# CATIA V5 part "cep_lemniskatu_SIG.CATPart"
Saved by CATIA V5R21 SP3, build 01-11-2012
Part number: cep_lemniskatu_SIG
Material "Steel": density 7860 kg/m3, Young's modulus 2e+11 Pa, Poisson ratio 0.266, thermal expansion 1.17e-05 1/K
Bounding box of the stored display mesh (mm): x -260 to 260, y -453.616 to 530, z 0 to 244
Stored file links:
  C:\Users\Martin\Desktop\vzduchove naklapeni\12\cep_lemniskatu_SIG.CATPart
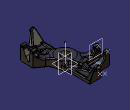
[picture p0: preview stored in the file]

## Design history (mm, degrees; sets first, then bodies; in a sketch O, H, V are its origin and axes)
Set1
  Plane1: type Offset, RefPlane zx-plane, Offset 400
  Plane2: type Offset, RefPlane face of Pad3, Offset 50
  Point1: (0, 0, 0)
  Line1: type PtDir, RefPoint Point1, Direction edge [face of Pad2 from Sketch2.L4 | start face of Pad2], Start 0, End 244
  Plane3: type Angle, RefPlane yz-plane, Direction Line1, Angle 45
  Line2: stored without definition
  Point2: stored without definition
  Plane4: type Offset, RefPlane face of Pad4, Offset 15
  Point3: (0, 470, 150)
  Point4: (0, 460, 110)
  Point5: type Center, Curve edge [face of Pad4 | face of Hole2]
  Point6: type Center, Curve edge [face of Pad4 | face of Hole1]
  Point7: type Between, FirstPoint Point6, SecondPoint Point5, Ratio 0.5
  Line3: type PtDir, RefPoint Point7, Direction edge [face of Pad5 from Sketch6.L1 | face of Pad4], Start -149, End 244
  Plane5: type 2Lines, Element1 Line3, Element2 Line1
  Plane6: type Offset, RefPlane face of Pad6, Offset 30
Body1 (main body)
  Sketch1 on xy-plane, origin (0, 0, 0), H (1, 0, 0), V (0, 1, 0)
    circle A1 centre (0, 0) radius 55
    circle A2 centre (0, 0) radius 115
    radius A1 = 55
    radius A2 = 115
  Pad1: profile Sketch1, direction (0, 0, 1), length 110
  Sketch2 on Plane1, origin (0, 400, 0), H (-1, 0, 0), V (0, 0, 1)
    line L1 (-45, 30) -> (45, 30)
    line L2 (75, 45) -> (75, 0)
    line L3 (75, 0) -> (-75, 0)
    line L4 (-75, 0) -> (-75, 45)
    reference projected line E1 (-115, 0) -> (115, 0) from edge [start face of Pad1 | face of Pad1 from Sketch1.A2]
    reference projected line E2 through (0, 0) direction (0, 1) from axis of face of Pad1 from Sketch1.A2
    reference projected line E3 (-115, 0) -> (115, 0) from edge [start face of Pad1 | face of Pad1 from Sketch1.A2]
    line L5 (-45, 45) -> (-45, 30)
    line L6 (45, 45) -> (75, 45)
    line L7 (45, 30) -> (45, 45)
    point P7 (75, 45)
    line L8 (-75, 45) -> (-45, 45)
    distance L4 L2 = 150
    distance E2 L4 = 75
    distance L1 E3 = 30
    distance L1 L6 = 15
    distance L5 L4 = 30
    distance L7 L2 = 30
    distance L8 L1 = 15
    horizontal: L1 H, L3 H, L6 H, L8 H
    vertical: L2 V, L4 V, L5 V, L7 V
    coincidence: E1 L3, P7 L6
  Pad2: profile Sketch2, direction (0, 1, 0), up to the existing solid (limit type 2)
  Sketch3 on face of Pad2, origin (-75, 0, 0), H (0, -1, 0), V (0, 0, 1)
    line L1 (-325, 45) -> (-280, 45)
    line L2 (-280, 45) -> (-280, 40)
    line L3 (-160, 0) -> (-325, 0)
    line L4 (-325, 0) -> (-325, 45)
    line L5 (-205, 45) -> (-160, 45)
    line L6 (-160, 45) -> (-160, 0)
    line L7 (-205, 40) -> (-205, 45)
    line L8 (-280, 40) -> (-205, 40)
    reference projected line E1 (-400, 0) -> (-87.178, 0) from edge [face of Pad2 | face of Pad2]
    reference projected line E2 through (0, 0) direction (0, 1) from axis of face of Pad1 from Sketch1.A1
    reference projected line E3 (-400, 45) -> (-87.178, 45) from edge [face of Pad2 from Sketch2.L2 | face of Pad2 from Sketch2.L6]
    reference projected line E4 (-400, 45) -> (-87.178, 45) from edge [face of Pad2 from Sketch2.L2 | face of Pad2 from Sketch2.L6]
    distance L8 L3 = 40
    distance L7 L6 = 45
    distance L4 L2 = 45
    distance E2 L6 = 160
    distance L2 L7 = 75
    horizontal: L1 H, L3 H, L5 H, L8 H
    vertical: L2 V, L4 V, L6 V, L7 V
    coincidence: L3 E1, L1 E3, L5 E4
  Pad3: profile Sketch3, direction (-1, 0, 0), length 185
  Sketch4 on face of Pad3 from Sketch3.L1, origin (0, 0, 45), H (1, 0, 0), V (0, 1, 0)
    line L1 (-260, 325) -> (-200, 325)
    line L2 (-200, 280) -> (-260, 280)
    line L3 (-260, 280) -> (-260, 325)
    reference projected line E1 (-75, 325) -> (-260, 325) from edge [face of Pad3 from Sketch3.L4 | face of Pad3 from Sketch3.L1]
    reference projected line E2 (-75, 280) -> (-260, 280) from edge [face of Pad3 from Sketch3.L1 | face of Pad3 from Sketch3.L2]
    reference projected line E3 (-260, 280) -> (-260, 325) from edge [face of Pad3 from Sketch3.L1 | end face of Pad3]
    point P3 (-260, 205)
    line L4 (-260, 205) -> (-200, 205)
    line L5 (-200, 160) -> (-260, 160)
    line L6 (-260, 160) -> (-260, 205)
    reference projected line E4 (-75, 160) -> (-260, 160) from edge [face of Pad3 | face of Pad3 from Sketch3.L6]
    reference projected line E5 (-75, 205) -> (-260, 205) from edge [face of Pad3 from Sketch3.L7 | face of Pad3]
    reference projected line E6 (-260, 160) -> (-260, 205) from edge [face of Pad3 | face of Pad3]
    point P5 (-208, 205)
    point P6 (-200, 280)
    line L7 (-200, 325) -> (-200, 280)
    line L8 (-200, 160) -> (-200, 205)
    distance P5 P3 = 52
    distance P6 L3 = 60
    horizontal: L1 H, L2 H, L4 H, L5 H
    vertical: L3 V, L6 V, L7 V, L8 V
    coincidence: L1 E1, L2 E2, E3 L3, L5 E4, L4 E5, E6 L6, P5 L4, L8 L7
  Pad4: profile Sketch4, direction (0, 0, 1), length 140
  Sketch5 on face of Pad4, origin (-260, 321.6842, 147.6114), H (0, 1, 0), V (0, 0, -1)
    point P1 (-11.6842, -17.3886)
    reference projected line E1 (3.3158, 102.6114) -> (3.3158, 147.6114) from edge [face of Pad4 | face of Pad4]
    reference projected line E2 (-116.6842, -37.3886) -> (-161.6842, -37.3886) from edge [face of Pad4 | end face of Pad4]
    distance P1 E1 = 15
    distance P1 E2 = 20
  Hole1: placed by Sketch5, at (-260, 310, 165) direction (1, 0, 0), diameter 20, depth 44
  Sketch6 on Plane2, origin (0, 0, 50), H (1, 0, 0), V (0, 1, 0)
    line L1 (-260, 160) -> (-104.837, 47.2675)
    line L2 (-75, 160) -> (-75, 87.178)
    projected circle E1 centre (0, 0) radius 115 from edge [face of Pad1 from Sketch1.A2 | end face of Pad1]
    projected arc E2 centre (0, 0) radius 115 from (-75, 87.178) to (-104.837, 47.2675) ccw from edge [face of Pad1 from Sketch1.A2 | end face of Pad1]
    point P1 (-260, 160)
    point P3 (-75, 87.178)
    point P4 (-75, 160)
    construction line L3 (-251.8954, 176.379) -> (48.2139, -33.7597)
    reference projected point E3 (-260, 160) from vertex [face of Pad4 | end face of Pad4 | face of Pad4]
    reference projected point E4 (-75, 87.178) from vertex [face of Pad2 from Sketch2.L2 | face of Pad3 | face of Pad1 from Sketch1.A2]
    reference projected point E5 (-75, 160) from vertex [face of Pad3 from Sketch3.L6 | face of Pad2 from Sketch2.L2 | face of Pad3]
    projected line E6 (-260, 160) -> (-200, 160) from edge [face of Pad4 | end face of Pad4]
    projected line E7 (-75, 160) -> (-200, 160) from edge [face of Pad3 | face of Pad4]
    angle L1 L3 = 1
    angle L3 H = 35
    coincidence: P1 E3, L3 O, P3 E4, P4 E5
  Pad5: profile Sketch6, direction (0, 0, 1), length 40, opposite side length 50
  Sketch7 on face of Pad4, origin (-260, 177.7691, 148.1263), H (0, 1, 0), V (0, 0, -1)
    point P1 (2.2309, -16.8737)
    reference projected line E1 (27.2309, -36.8737) -> (-17.7691, -36.8737) from edge [face of Pad4 | end face of Pad4]
    reference projected line E3 (27.2309, 103.1263) -> (27.2309, 108.1263) from edge [face of Pad4 | face of Pad4]
    distance P1 E1 = 20
    distance P1 E3 = 25
  Hole2: placed by Sketch7, at (-260, 180, 165) direction (1, 0, 0), diameter 20, depth 44
  Sketch8 on face of Pad4 from Sketch4.L8, origin (-200, 0, 0), H (0, 1, 0), V (0, 0, 1)
    line L1 (160, 90) -> (205, 90)
    line L2 (205, 90) -> (205, 45)
    reference projected line E1 (160, 90) -> (47.2675, 90) from edge [face of Pad5 from Sketch6.L1 | end face of Pad5]
    reference projected line E2 (205, 45) -> (205, 185) from edge [face of Pad4 | face of Pad4 from Sketch4.L8]
    projected line E3 (160, 45) -> (205, 45) from edge [face of Pad3 | face of Pad4 from Sketch4.L8]
    projected line E4 (160, 45) -> (160, 90) from edge [face of Pad4 from Sketch4.L8 | face of Pad5 from Sketch6.E7]
    horizontal: L1 H
    vertical: L2 V
    coincidence: E1 L1, L2 E2
  Pad6: profile Sketch8, direction (1, 0, 0), up to face of Pad2 from Sketch2.L2
  Sketch9 on face of Pad4, origin (0, 205, 0), H (-1, 0, 0), V (0, 0, 1)
    line L1 (45, 90) -> (75, 90)
    line L2 (45, 90) -> (45, 45)
    reference projected line E1 (45, 45) -> (45, 30) from edge [face of Pad1 from Sketch1.A2 | face of Pad2 from Sketch2.L7]
    reference projected line E2 (200, 90) -> (75, 90) from edge [face of Pad6 | face of Pad4]
    projected line E3 (45, 45) -> (75, 45) from edge [face of Pad3 | face of Pad1 from Sketch1.A2]
    projected line E4 (45, 45) -> (75, 45) from edge [face of Pad3 | face of Pad1 from Sketch1.A2]
    point P2 (75, 45)
    projected line E5 (75, 90) -> (75, 45) from edge [end face of Pad6 | face of Pad4]
    projected line E6 (75, 90) -> (75, 45) from edge [end face of Pad6 | face of Pad4]
    point P4 (75, 45)
    horizontal: L1 H
    vertical: L2 V
    coincidence: L2 E1, L1 E2, P2 P4
  Pad7: profile Sketch9, direction (0, -1, 0), up to the existing solid (limit type 2)
  Sketch10 on face of Pad2 from Sketch2.L2, origin (-75, 0, 0), H (0, -1, 0), V (0, 0, 1)
    line L1 (-205, 90) -> (-280, 45)
    point P1 (-205, 90)
    point P2 (-280, 45)
    reference projected point E1 (-280, 45) from vertex [face of Pad3 from Sketch3.L2 | face of Pad2 from Sketch2.L2 | face of Pad3]
    reference projected point E2 (-205, 90) from vertex [face of Pad7 | face of Pad7 | face of Pad7]
    coincidence: P2 E1, E2 P1
  Stiffener1: ExtendedProfile Sketch10, ThicknessTop 0, ThicknessValue 30
  Sketch11 on face of Pad4, origin (0, 280, 0), H (1, 0, 0), V (0, 0, 1)
    line L1 (-200, 105) -> (-140, 45)
    point P1 (-200, 105)
    point P2 (-140, 45)
    reference projected line E1 (-200, 45) -> (-200, 185) from edge [face of Pad4 from Sketch4.L7 | face of Pad4]
    reference projected line E2 (-75, 45) -> (-260, 45) from edge [face of Pad3 | face of Pad4]
    reference projected line E3 (-75, 45) -> (-260, 45) from edge [face of Pad3 | face of Pad4]
    reference projected line E4 (-200, 45) -> (-200, 185) from edge [face of Pad4 from Sketch4.L7 | face of Pad4]
    angle E3 L1 = 45
    distance P2 E4 = 60
    coincidence: P1 E1, P2 E2
  Stiffener2: ExtendedProfile Sketch11, ThicknessTop 0, ThicknessValue 40
  Sketch12 on yz-plane, origin (0, 0, 0), H (0, 1, 0), V (0, 0, 1)
    line L1 (400, 0) -> (427.8346, 198.0536)
    point P1 (400, 0)
    projected line E1 (400, 0) -> (400, 45) from edge [face of Pad2 from Sketch2.L2 | start face of Pad2]
    point P3 (400, 0)
    line L2 (427.8346, 198.0536) -> (415.3104, 199.8138)
    line L3 (415.3104, 199.8138) -> (334.4075, 9.2184)
    line L4 (334.4075, 9.2184) -> (400, 0)
    angle E1 L1 = 8
    distance L4 L2 = 200
    angle L3 L4 = 75
    coincidence: P1 P3
    perpendicularity: L2 L1, L4 L1
  Pad8: profile Sketch12, direction (1, 0, 0), length 75, mirrored extent
  Sketch13 on face of Pad8 from Sketch12.L1, origin (0, 392.2523, -55.1275), H (-1, 0, 0), V (0, 0.1392, 0.9903)
    circle A1 centre (0, 225.6692) radius 30
    point P1 (0, 225.6692)
    point P2 (0, 255.6692)
    reference projected line E1 (75, 255.6692) -> (-75, 255.6692) from edge [face of Pad8 from Sketch12.L2 | face of Pad8 from Sketch12.L1]
    radius A1 = 30
    coincidence: P1 V, A1 P2, P2 V
    tangency: A1 E1
  Pad9: profile Sketch13, direction (0, 0.9903, -0.1392), length 30
  Fillet1: radius 30, on edge [face of Pad9 from Sketch13.A1 | end face of Pad9]
  Sketch14 on face of Pad8 from Sketch12.L1, origin (0, 392.2523, -55.1275), H (-1, 0, 0), V (0, 0.1392, 0.9903)
    line L1 (28.5068, 235.016) -> (75, 93.2164)
    projected line E1 (75, 55.6692) -> (75, 255.6692) from edge [face of Pad8 | face of Pad8 from Sketch12.L1]
    projected line E2 (75, 93.2164) -> (75, 255.6692) from edge [face of Pad8 | face of Pad8 from Sketch12.L1]
    point P1 (75, 55.6692)
    point P2 (75, 255.6692)
    projected line E3 (75, 255.6692) -> (-75, 255.6692) from edge [face of Pad8 from Sketch12.L2 | face of Pad8 from Sketch12.L1]
    projected line E4 (75, 255.6692) -> (0, 255.6692) from edge [face of Pad8 from Sketch12.L2 | face of Pad8 from Sketch12.L1]
    point P3 (75, 255.6692)
    point P4 (-75, 255.6692)
    reference projected circle E5 centre (0, 225.6692) radius 30 from edge [face of Pad8 from Sketch12.L1 | face of Fillet1]
    projected circle E6 centre (0, 225.6692) radius 30 from edge [face of Pad8 from Sketch12.L1 | face of Fillet1]
    projected arc E7 centre (0, 225.6692) radius 30 from (28.5068, 235.016) to (0, 255.6692) ccw from edge [face of Pad8 from Sketch12.L1 | face of Fillet1]
    point P5 (75, 93.2164)
    point P6 (28.5068, 235.016)
    point P7 (0, 255.6692)
    reference projected line E8 (0, 241.6254) -> (0, 0) from edge of Line1
    point P10 (-75, 255.6692)
    point P11 (-75, 255.6692)
    point P12 (0, 255.6692)
    point P13 (-28.5068, 235.016)
    point P14 (-75, 93.2164)
    line L2 (-28.5068, 235.016) -> (-75, 93.2164)
    point P15 (-75, 55.6692)
    point P16 (75, 255.6692)
    construction circle A1 centre (0, 225.6692) radius 30
    arc A2 centre (0, 225.6692) radius 30 from (-28.5068, 235.016) to (0, 255.6692) cw
    construction line L3 (-75, 55.6692) -> (-75, 255.6692)
    line L4 (-75, 93.2164) -> (-75, 255.6692)
    construction line L5 (-75, 255.6692) -> (75, 255.6692)
    line L6 (-75, 255.6692) -> (0, 255.6692)
    reference projected point E9 (75, 93.2164) from vertex [face of Pad3 | face of Pad8 from Sketch12.L3 | face of Pad8]
    tangency: E5 L1
    coincidence: P2 P3, P5 E9
    symmetry: P2 P10 E8, P3 P11 E8, P7 P12 E8, P6 P13 E8, E6 A1 E8, P5 P14 E8, L1 L2 E8, P1 P15 E8, E1 L3 E8, P4 P16 E8, E3 L5 E8, E6 A2 E8, E1 L4 E8, E3 L6 E8
  Pocket1: profile Sketch14, direction (0, -0.9903, 0.1392), through (limit type 6)
  Fillet2: radius 12, on edge [face of Pad8 | face of Stiffener2]
  Fillet3: radius 15, on edge [face of Stiffener1 | face of Pad8 from Sketch12.L3]
  Fillet4: radius 15, on edge [face of Pad2 from Sketch2.L5 | face of Pad8 from Sketch12.L3]
  Fillet5: radius 100, on edge [face of Stiffener2 | face of Pad4 from Sketch4.L7]
  Fillet6: on edge [face of Pad3 | face of Stiffener2]
  Fillet7: radius 15, on edge [face of Pad4 from Sketch4.L8 | face of Pad4]
  Fillet8: radius 120, on edge [face of Pad1 from Sketch1.A2 | face of Pad5 from Sketch6.L1]
  Fillet9: on edge [face of Pad8 from Sketch12.L1 | face of Fillet1]
  Fillet10: on edge [face of Pad1 from Sketch1.A2 | face of Pad8]
  Chamfer1: length 50, angle 45, on edge [face of Pad6 | face of Fillet7]
  Fillet11: on edge [face of Fillet7 | face of Chamfer1]
  Chamfer2: length 80, angle 35, on edge [face of Stiffener2 | face of Pad3 from Sketch3.L8]
  Fillet12: radius 15, on edge [face of Stiffener1 | face of Pad7]
  Fillet13: on edge [face of Pad5 | face of Stiffener2]
  Fillet14: radius 10, on edge [face of Pad8 | face of Pocket1 from Sketch14.L1]
  Fillet15: radius 10, on edge [face of Pad3 | face of Pad8 from Sketch12.L3]
  Fillet16: radius 10, on edge [face of Pad8 from Sketch12.L3 | face of Pocket1 from Sketch14.L1]
  Fillet17: radius 10, on edge [face of Pad2 from Sketch2.L8 | face of Fillet16]
  Fillet18: radius 5, on edge [face of Pad8 from Sketch12.L1 | face of Pocket1 from Sketch14.L1]
  Fillet19: radius 5, on edge [face of Fillet8 | face of Pad5]
  Chamfer3: length 65, angle 10, on edge [face of Stiffener2 | end face of Pad4]
  Chamfer4: length 60, angle 10, on edge [face of Pad4 | end face of Pad4]
  Fillet20: radius 100, on edge [face of Pad4 | face of Chamfer4]
  Fillet21: radius 200, on edge [face of Chamfer2 | face of Chamfer3]
  Chamfer5: length 20, angle 70, on edge [face of Pad6 | face of Pad1 from Sketch1.A2]
  Chamfer6: length 60, angle 65, on edge [face of Stiffener1 | face of Pad1 from Sketch1.A2]
  FaceFillet1: ConicRatio 0.5, Face1 face of Chamfer1, Face2 face of Chamfer5, Radius 100
  Fillet22: radius 60, on edge [face of FaceFillet1 | face of Pad7]
  Fillet23: radius 15, on edge [face of Chamfer2 | face of Fillet6]
  Fillet24: radius 15, on edge [face of Pad3 from Sketch3.L8 | face of Pad7]
  FaceFillet2: ConicRatio 0.5, Face1 face of Chamfer6, Face2 face of Pad2 from Sketch2.L5, Radius 30
  Fillet25: radius 120, conic ratio 0.5, on edge [face of Pad1 from Sketch1.A2 | face of Chamfer6]
  Fillet26: radius 15, conic ratio 0.5, on edge [face of Fillet25 | face of Chamfer5]
  Fillet27: radius 20, on edge [face of Fillet25 | face of Pad2 from Sketch2.L8]
  Fillet28: radius 10, on edge [face of Pad7 | face of Pad7]
  Fillet29: radius 100, on edge [face of Stiffener1 from Sketch10.L1 | face of Pad3]
  Fillet30: radius 200, on edge [face of Chamfer6 | face of Stiffener1]
  Fillet31: radius 10, on edge [face of Chamfer6 | face of Pad2 from Sketch2.L1]
  Fillet32: radius 10, on edge [face of Fillet30 | face of Pad3]
  Fillet33: radius 10, on edge [face of Pad3 | face of Fillet32]
  Fillet34: radius 10, on edge [face of Fillet27 | face of FaceFillet2]
  Fillet35: radius 10, on edge [face of Pad2 from Sketch2.L8 | face of Pad8]
  CircPattern1: of the body so far, instances 2, angular step 180, axis from Line1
